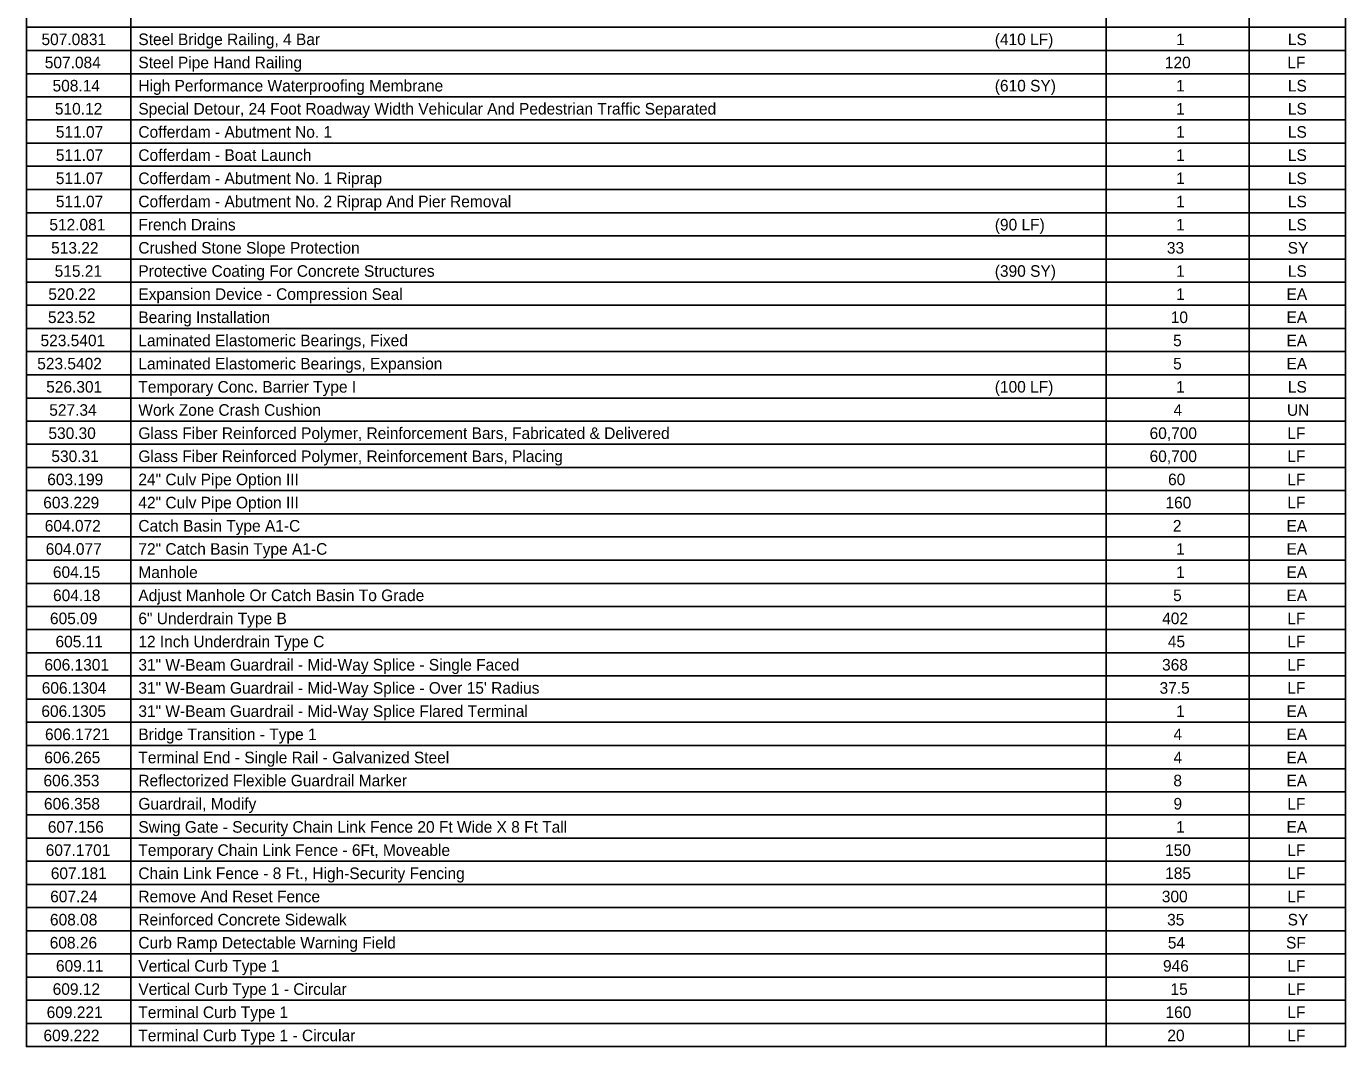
# Model space of a CAD drawing. Extents: x 1005753.14 to 1005755.85, y 326152.24 to 326153.97.
# Drawn here: x 1005753.141 to 1005754.261, y 326152.241 to 326153.108 of the extents above; entities that cross this region are included whole.
import ezdxf

# ---------------------------------------------------------------- set-up
doc = ezdxf.new("R2010")
doc.units = 0
doc.layers.add('ANNOTATION', color=7, linetype='Continuous')
doc.layers.add('BORDER', color=7, linetype='Continuous')

msp = doc.modelspace()

# ---------------------------------------------------------------- linework, layer by layer
at = {"layer": 'BORDER'}
for p, q in [((1005753.2293, 326153.954), (1005753.2293, 326152.2413)), ((1005754.058, 326153.954), (1005754.058, 326152.2413)), ((1005754.1794, 326153.954), (1005754.1794, 326152.2413)), ((1005753.1407, 326153.1075), (1005754.2614, 326153.1075)), ((1005753.1407, 326153.0878), (1005754.2614, 326153.0878)), ((1005753.1407, 326153.0681), (1005754.2614, 326153.0681)), ((1005753.1407, 326153.0484), (1005754.2614, 326153.0484)), ((1005753.1407, 326153.0288), (1005754.2614, 326153.0288)), ((1005753.1407, 326153.0091), (1005754.2614, 326153.0091)), ((1005753.1407, 326152.9894), (1005754.2614, 326152.9894)), ((1005753.1407, 326152.9697), (1005754.2614, 326152.9697)), ((1005753.1407, 326152.95), (1005754.2614, 326152.95)), ((1005753.1407, 326152.9303), (1005754.2614, 326152.9303)), ((1005753.1407, 326152.9106), (1005754.2614, 326152.9106)), ((1005753.1407, 326152.891), (1005754.2614, 326152.891)), ((1005753.1407, 326152.8713), (1005754.2614, 326152.8713)), ((1005753.1407, 326152.8516), (1005754.2614, 326152.8516)), ((1005753.1407, 326152.8319), (1005754.2614, 326152.8319)), ((1005753.1407, 326152.8122), (1005754.2614, 326152.8122)), ((1005753.1407, 326152.7925), (1005754.2614, 326152.7925)), ((1005753.1407, 326152.7728), (1005754.2614, 326152.7728)), ((1005753.1407, 326152.7532), (1005754.2614, 326152.7532)), ((1005753.1407, 326152.7335), (1005754.2614, 326152.7335)), ((1005753.1407, 326152.7138), (1005754.2614, 326152.7138)), ((1005753.1407, 326152.6941), (1005754.2614, 326152.6941)), ((1005753.1407, 326152.6744), (1005754.2614, 326152.6744)), ((1005753.1407, 326152.6547), (1005754.2614, 326152.6547)), ((1005753.1407, 326152.635), (1005754.2614, 326152.635)), ((1005753.1407, 326152.6153), (1005754.2614, 326152.6153)), ((1005753.1407, 326152.5957), (1005754.2614, 326152.5957)), ((1005753.1407, 326152.576), (1005754.2614, 326152.576)), ((1005753.1407, 326152.5563), (1005754.2614, 326152.5563)), ((1005753.1407, 326152.5366), (1005754.2614, 326152.5366)), ((1005753.1407, 326152.5169), (1005754.2614, 326152.5169)), ((1005753.1407, 326152.4972), (1005754.2614, 326152.4972)), ((1005753.1407, 326152.4775), (1005754.2614, 326152.4775)), ((1005753.1407, 326152.4579), (1005754.2614, 326152.4579)), ((1005753.1407, 326152.4382), (1005754.2614, 326152.4382)), ((1005753.1407, 326152.4185), (1005754.2614, 326152.4185)), ((1005753.1407, 326152.3988), (1005754.2614, 326152.3988)), ((1005753.1407, 326152.3791), (1005754.2614, 326152.3791)), ((1005753.1407, 326152.3594), (1005754.2614, 326152.3594)), ((1005753.1407, 326152.3397), (1005754.2614, 326152.3397)), ((1005753.1407, 326152.3201), (1005754.2614, 326152.3201)), ((1005753.1407, 326152.3004), (1005754.2614, 326152.3004)), ((1005753.1407, 326152.2807), (1005754.2614, 326152.2807)), ((1005753.1407, 326152.261), (1005754.2614, 326152.261))]:
    msp.add_line(p, q, dxfattribs=at)
msp.add_lwpolyline([(1005753.1407, 326153.9737), (1005754.2614, 326153.9737), (1005754.2614, 326152.2413), (1005753.1407, 326152.2413)], close=True, dxfattribs=at)

# ---------------------------------------------------------------- texts
at = {"layer": 'ANNOTATION'}
for s, height, p in [('507.0831', 0.00984, (1005753.1535, 326153.0924)), ('Steel Bridge Railing, 4 Bar', 0.009843, (1005753.2358, 326153.0924)), ('(410 LF)', 0.00984, (1005753.9634, 326153.0924)), ('1', 0.00984, (1005754.1175, 326153.0924)), ('LS', 0.00984, (1005754.2124, 326153.0924)), ('507.084', 0.00984, (1005753.1563, 326153.0727)), ('Steel Pipe Hand Railing', 0.009843, (1005753.2358, 326153.0727)), ('120', 0.00984, (1005754.1079, 326153.0727)), ('LF', 0.00984, (1005754.2119, 326153.0727)), ('508.14', 0.00984, (1005753.1629, 326153.053)), ('High Performance Waterproofing Membrane', 0.009843, (1005753.2358, 326153.053)), ('(610 SY)', 0.00984, (1005753.9634, 326153.053)), ('1', 0.00984, (1005754.1175, 326153.053)), ('LS', 0.00984, (1005754.2124, 326153.053)), ('510.12', 0.00984, (1005753.1649, 326153.0334)), ('Special Detour, 24 Foot Roadway Width Vehicular And Pedestrian Traffic Separated', 0.009843, (1005753.2358, 326153.0334)), ('1', 0.00984, (1005754.1175, 326153.0334)), ('LS', 0.00984, (1005754.2124, 326153.0334)), ('511.07', 0.00984, (1005753.1657, 326153.0137)), ('Cofferdam - Abutment No. 1', 0.009843, (1005753.2358, 326153.0137)), ('1', 0.00984, (1005754.1175, 326153.0137)), ('LS', 0.00984, (1005754.2124, 326153.0137)), ('511.07', 0.00984, (1005753.1657, 326152.994)), ('Cofferdam - Boat Launch', 0.009843, (1005753.2358, 326152.994)), ('1', 0.00984, (1005754.1175, 326152.994)), ('LS', 0.00984, (1005754.2124, 326152.994)), ('511.07', 0.00984, (1005753.1657, 326152.9743)), ('Cofferdam - Abutment No. 1 Riprap', 0.009843, (1005753.2358, 326152.9743)), ('1', 0.00984, (1005754.1175, 326152.9743)), ('LS', 0.00984, (1005754.2124, 326152.9743)), ('511.07', 0.00984, (1005753.1657, 326152.9546)), ('Cofferdam - Abutment No. 2 Riprap And Pier Removal', 0.009843, (1005753.2358, 326152.9546)), ('1', 0.00984, (1005754.1175, 326152.9546)), ('LS', 0.00984, (1005754.2124, 326152.9546)), ('512.081', 0.00984, (1005753.1602, 326152.9349)), ('French Drains', 0.009843, (1005753.2358, 326152.9349)), ('(90 LF)', 0.00984, (1005753.9634, 326152.9349)), ('1', 0.00984, (1005754.1175, 326152.9349)), ('LS', 0.00984, (1005754.2124, 326152.9349)), ('513.22', 0.00984, (1005753.1617, 326152.9152)), ('Crushed Stone Slope Protection', 0.009843, (1005753.2358, 326152.9152)), ('33', 0.00984, (1005754.1096, 326152.9152)), ('SY', 0.00984, (1005754.2122, 326152.9152)), ('515.21', 0.00984, (1005753.1647, 326152.8955)), ('Protective Coating For Concrete Structures', 0.009843, (1005753.2358, 326152.8955)), ('(390 SY)', 0.00984, (1005753.9634, 326152.8955)), ('1', 0.00984, (1005754.1175, 326152.8955)), ('LS', 0.00984, (1005754.2124, 326152.8955)), ('520.22', 0.00984, (1005753.1593, 326152.8759)), ('Expansion Device - Compression Seal', 0.009843, (1005753.2358, 326152.8759)), ('1', 0.00984, (1005754.1175, 326152.8759)), ('EA', 0.00984, (1005754.2112, 326152.8759)), ('523.52', 0.00984, (1005753.159, 326152.8562)), ('Bearing Installation', 0.009843, (1005753.2358, 326152.8562)), ('10', 0.00984, (1005754.1129, 326152.8562)), ('EA', 0.00984, (1005754.2112, 326152.8562)), ('Laminated Elastomeric Bearings, Fixed', 0.009843, (1005753.2358, 326152.8365)), ('523.5401', 0.00984, (1005753.1527, 326152.8365)), ('5', 0.00984, (1005754.1149, 326152.8365)), ('EA', 0.00984, (1005754.2112, 326152.8365)), ('523.5402', 0.00984, (1005753.1499, 326152.8168)), ('Laminated Elastomeric Bearings, Expansion', 0.009843, (1005753.2358, 326152.8168)), ('5', 0.00984, (1005754.1149, 326152.8168)), ('EA', 0.00984, (1005754.2112, 326152.8168)), ('526.301', 0.00984, (1005753.1575, 326152.7971)), ('Temporary Conc. Barrier Type I', 0.009843, (1005753.2358, 326152.7971)), ('(100 LF)', 0.00984, (1005753.9634, 326152.7971)), ('1', 0.00984, (1005754.1175, 326152.7971)), ('LS', 0.00984, (1005754.2124, 326152.7971)), ('527.34', 0.00984, (1005753.1601, 326152.7774)), ('Work Zone Crash Cushion', 0.009843, (1005753.2358, 326152.7774)), ('4', 0.00984, (1005754.1152, 326152.7774)), ('UN', 0.00984, (1005754.2116, 326152.7774)), ('Glass Fiber Reinforced Polymer, Reinforcement Bars, Fabricated & Delivered', 0.009843, (1005753.2358, 326152.7577)), ('530.30', 0.00984, (1005753.1594, 326152.7577)), ('60,700', 0.00984, (1005754.0949, 326152.7577)), ('LF', 0.00984, (1005754.2119, 326152.7577)), ('530.31', 0.00984, (1005753.1619, 326152.7381)), ('Glass Fiber Reinforced Polymer, Reinforcement Bars, Placing', 0.009843, (1005753.2358, 326152.7381)), ('60,700', 0.00984, (1005754.0949, 326152.7381)), ('LF', 0.00984, (1005754.2119, 326152.7381)), ('603.199', 0.00984, (1005753.1584, 326152.7184)), ('24" Culv Pipe Option III', 0.009843, (1005753.2358, 326152.7184)), ('60', 0.00984, (1005754.1106, 326152.7184)), ('LF', 0.00984, (1005754.2119, 326152.7184)), ('603.229', 0.00984, (1005753.155, 326152.6987)), ('42" Culv Pipe Option III', 0.009843, (1005753.2358, 326152.6987)), ('160', 0.00984, (1005754.1084, 326152.6987)), ('LF', 0.00984, (1005754.2119, 326152.6987)), ('604.072', 0.00984, (1005753.1563, 326152.679)), ('Catch Basin Type A1-C', 0.009843, (1005753.2358, 326152.679)), ('2', 0.00984, (1005754.1147, 326152.679)), ('EA', 0.00984, (1005754.2112, 326152.679)), ('604.077', 0.00984, (1005753.1571, 326152.6593)), ('72" Catch Basin Type A1-C', 0.009843, (1005753.2358, 326152.6593)), ('1', 0.00984, (1005754.1175, 326152.6593)), ('EA', 0.00984, (1005754.2112, 326152.6593)), ('604.15', 0.00984, (1005753.1632, 326152.6396)), ('Manhole', 0.00984, (1005753.2358, 326152.6396)), ('1', 0.00984, (1005754.1175, 326152.6396)), ('EA', 0.00984, (1005754.2112, 326152.6396)), ('604.18', 0.00984, (1005753.1633, 326152.6199)), ('Adjust Manhole Or Catch Basin To Grade', 0.009843, (1005753.2358, 326152.6199)), ('5', 0.00984, (1005754.1149, 326152.6199)), ('EA', 0.00984, (1005754.2112, 326152.6199)), ('605.09', 0.00984, (1005753.1607, 326152.6003)), ('6" Underdrain Type B', 0.009843, (1005753.2358, 326152.6003)), ('402', 0.00984, (1005754.1056, 326152.6003)), ('LF', 0.00984, (1005754.2119, 326152.6003)), ('605.11', 0.00984, (1005753.1654, 326152.5806)), ('12 Inch Underdrain Type C', 0.009843, (1005753.2358, 326152.5806)), ('45', 0.00984, (1005754.1104, 326152.5806)), ('LF', 0.00984, (1005754.2119, 326152.5806)), ('606.1301', 0.00984, (1005753.156, 326152.5609)), ('31" W-Beam Guardrail - Mid-Way Splice - Single Faced', 0.009843, (1005753.2358, 326152.5609)), ('368', 0.00984, (1005754.1055, 326152.5609)), ('LF', 0.00984, (1005754.2119, 326152.5609)), ('606.1304', 0.00984, (1005753.1537, 326152.5412)), ('31" W-Beam Guardrail - Mid-Way Splice - Over 15\' Radius', 0.009843, (1005753.2358, 326152.5412)), ('37.5', 0.00984, (1005754.1034, 326152.5412)), ('LF', 0.00984, (1005754.2119, 326152.5412)), ('606.1305', 0.00984, (1005753.1534, 326152.5215)), ('31" W-Beam Guardrail - Mid-Way Splice Flared Terminal', 0.009843, (1005753.2358, 326152.5215)), ('1', 0.00984, (1005754.1175, 326152.5215)), ('EA', 0.00984, (1005754.2112, 326152.5215)), ('606.1721', 0.00984, (1005753.1565, 326152.5018)), ('Bridge Transition - Type 1', 0.009843, (1005753.2358, 326152.5018)), ('4', 0.00984, (1005754.1152, 326152.5018)), ('EA', 0.00984, (1005754.2112, 326152.5018)), ('606.265', 0.00984, (1005753.1559, 326152.4821)), ('Terminal End - Single Rail - Galvanized Steel', 0.009843, (1005753.2358, 326152.4821)), ('4', 0.00984, (1005754.1152, 326152.4821)), ('EA', 0.00984, (1005754.2112, 326152.4821)), ('606.353', 0.00984, (1005753.1552, 326152.4625)), ('Reflectorized Flexible Guardrail Marker', 0.009843, (1005753.2358, 326152.4625)), ('8', 0.00984, (1005754.1151, 326152.4625)), ('EA', 0.00984, (1005754.2112, 326152.4625)), ('606.358', 0.00984, (1005753.1556, 326152.4428)), ('Guardrail, Modify', 0.009843, (1005753.2358, 326152.4428)), ('9', 0.00984, (1005754.1152, 326152.4428)), ('LF', 0.00984, (1005754.2119, 326152.4428)), ('607.156', 0.00984, (1005753.1589, 326152.4231)), ('Swing Gate - Security Chain Link Fence 20 Ft Wide X 8 Ft Tall', 0.009843, (1005753.2358, 326152.4231)), ('1', 0.00984, (1005754.1175, 326152.4231)), ('EA', 0.00984, (1005754.2112, 326152.4231)), ('607.1701', 0.00984, (1005753.1571, 326152.4034)), ('Temporary Chain Link Fence - 6Ft, Moveable', 0.009843, (1005753.2358, 326152.4034)), ('150', 0.00984, (1005754.108, 326152.4034)), ('LF', 0.00984, (1005754.2119, 326152.4034)), ('607.181', 0.00984, (1005753.1614, 326152.3837)), ('Chain Link Fence - 8 Ft., High-Security Fencing', 0.009843, (1005753.2358, 326152.3837)), ('185', 0.00984, (1005754.1081, 326152.3837)), ('LF', 0.00984, (1005754.2119, 326152.3837)), ('607.24', 0.00984, (1005753.1609, 326152.364)), ('Remove And Reset Fence', 0.009843, (1005753.2358, 326152.364)), ('300', 0.00984, (1005754.1053, 326152.364)), ('LF', 0.00984, (1005754.2119, 326152.364)), ('608.08', 0.00984, (1005753.1607, 326152.3443)), ('Reinforced Concrete Sidewalk', 0.009843, (1005753.2358, 326152.3443)), ('35', 0.00984, (1005754.1098, 326152.3443)), ('SY', 0.00984, (1005754.2122, 326152.3443)), ('608.26', 0.00984, (1005753.1605, 326152.3247)), ('Curb Ramp Detectable Warning Field', 0.009843, (1005753.2358, 326152.3247)), ('54', 0.00984, (1005754.1104, 326152.3247)), ('SF', 0.00984, (1005754.2108, 326152.3247)), ('609.11', 0.00984, (1005753.1658, 326152.305)), ('Vertical Curb Type 1', 0.009843, (1005753.2358, 326152.305)), ('946', 0.00984, (1005754.1063, 326152.305)), ('LF', 0.00984, (1005754.2119, 326152.305)), ('609.12', 0.00984, (1005753.163, 326152.2853)), ('Vertical Curb Type 1 - Circular', 0.009843, (1005753.2358, 326152.2853)), ('15', 0.00984, (1005754.1127, 326152.2853)), ('LF', 0.00984, (1005754.2119, 326152.2853)), ('609.221', 0.00984, (1005753.1579, 326152.2656)), ('Terminal Curb Type 1', 0.009843, (1005753.2358, 326152.2656)), ('160', 0.00984, (1005754.1084, 326152.2656)), ('LF', 0.00984, (1005754.2119, 326152.2656)), ('609.222', 0.00984, (1005753.1552, 326152.2459)), ('Terminal Curb Type 1 - Circular', 0.009843, (1005753.2358, 326152.2459)), ('20', 0.00984, (1005754.11, 326152.2459)), ('LF', 0.00984, (1005754.2119, 326152.2459))]:
    msp.add_text(s, height=height, dxfattribs=at).set_placement(p)

doc.saveas('drawing.dxf')
